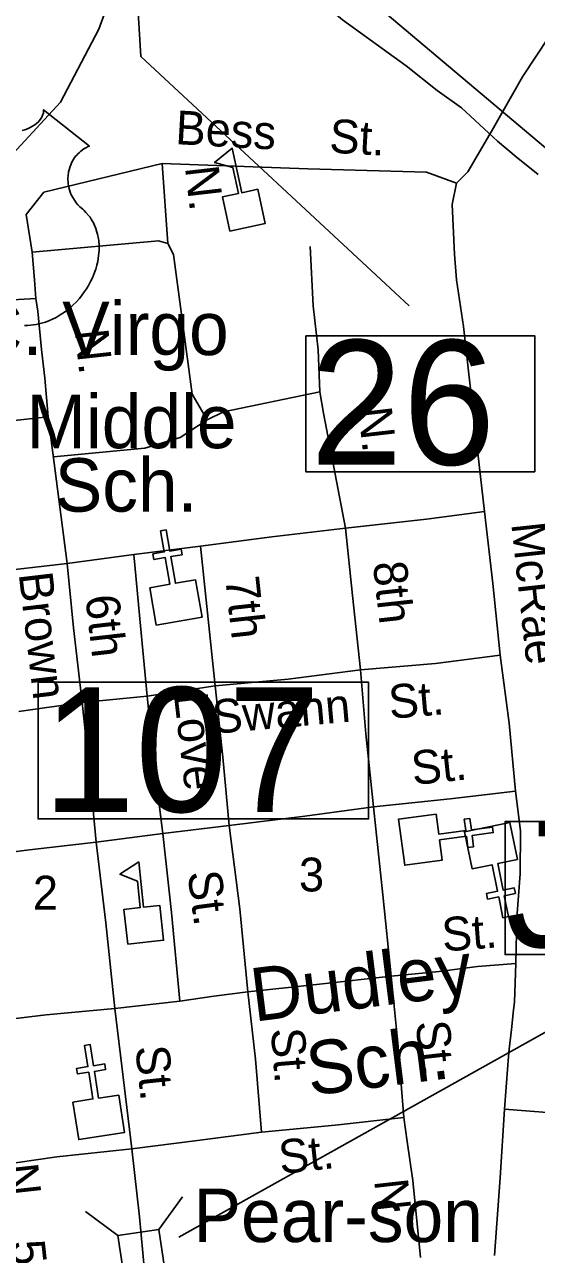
# Model space of a CAD drawing. Extents: x 2290055 to 2389491, y 66597 to 237875.
# Drawn here: x 2319151 to 2320590, y 181498 to 184954 of the extents above; entities that cross this region are included whole.
import ezdxf

# ---------------------------------------------------------------- set-up
doc = ezdxf.new("R2010")
doc.units = 0
for name, color, linetype in [('Exist Cultural Church CELL', 7, 'Continuous'), ('Exist Cultural Educational Facility High CELL', 7, 'Continuous'), ('Exist Cultural Educational Facility High Label', 7, 'Continuous'), ('Exist Cultural Educational Facility Middle CELL', 7, 'Continuous'), ('Exist Cultural Educational Facility Middle Label', 7, 'Continuous'), ('Exist Railroad Mainline', 7, 'Continuous'), ('Exist Road Non-System Structure Non-Sys Other CELL', 7, 'Continuous'), ('Exist Road Non-System Structure Non-Sys Other Number Label', 7, 'Continuous'), ('Exist Road Non-System Type 51', 7, 'Continuous'), ('Exist Road Non-System Type 51 Label', 7, 'Continuous'), ('Exist Road Primary US Shield CELL', 7, 'Continuous'), ('Exist Road Primary US Structure Cantilever Sign Number Label', 7, 'Continuous'), ('Exist Road Primary US Structure Standard Bridge Number Label', 7, 'Continuous')]:
    doc.layers.add(name, color=color, linetype=linetype)

msp = doc.modelspace()

# ---------------------------------------------------------------- linework, layer by layer
at = {"layer": 'Exist Cultural Church CELL'}
for points in [[(2319502.8, 183371.6), (2319558.9, 183381.3), (2319546, 183456.4), (2319514.4, 183450.9), (2319511.7, 183466.7), (2319543.3, 183472.1), (2319533.1, 183531.4), (2319548.9, 183534.1), (2319559, 183474.8), (2319590.6, 183480.2), (2319593.3, 183464.5), (2319561.8, 183459.1), (2319574.7, 183384), (2319631.5, 183393.7), (2319649.5, 183288.8), (2319520.8, 183266.6)], [(2320307.9, 182735.2), (2320315.5, 182678.8), (2320391, 182688.9), (2320386.7, 182720.6), (2320402.6, 182722.7), (2320406.8, 182691), (2320466.4, 182698.9), (2320468.5, 182683.1), (2320408.9, 182675.1), (2320413.1, 182643.4), (2320397.3, 182641.3), (2320393.1, 182673), (2320317.6, 182662.9), (2320325.1, 182605.8), (2320219.6, 182591.7), (2320202.3, 182721.1)], [(2320536.7, 182607.7), (2320481, 182596.2), (2320496.2, 182521.6), (2320527.6, 182528), (2320530.8, 182512.4), (2320499.4, 182506), (2320511.5, 182447), (2320495.8, 182443.8), (2320483.7, 182502.7), (2320452.4, 182496.3), (2320449.2, 182512), (2320480.5, 182518.4), (2320465.3, 182593), (2320408.8, 182581.6), (2320387.5, 182685.9), (2320515.4, 182712)], [(2319286.5, 181925.6), (2319342.7, 181934.5), (2319331.1, 182009.7), (2319299.4, 182004.8), (2319297, 182020.6), (2319328.6, 182025.5), (2319319.4, 182084.9), (2319335.2, 182087.4), (2319344.5, 182027.9), (2319376.1, 182032.9), (2319378.5, 182017.1), (2319346.9, 182012.2), (2319358.6, 181936.9), (2319415.6, 181945.7), (2319431.9, 181840.5), (2319302.8, 181820.4)]]:
    msp.add_lwpolyline(points, close=True, dxfattribs=at)
at = {"layer": 'Exist Cultural Educational Facility High CELL'}
msp.add_lwpolyline([(2319440.5, 182370), (2319430.1, 182467.4), (2319475.9, 182472.3), (2319467.9, 182547), (2319418.5, 182566.1), (2319471.7, 182601.1), (2319485.4, 182473.3), (2319531.2, 182478.2), (2319541.6, 182380.9)], close=True, dxfattribs=at)
at = {"layer": 'Exist Cultural Educational Facility Middle CELL'}
msp.add_lwpolyline([(2319727.9, 184374.2), (2319707.1, 184469.9), (2319752.1, 184479.6), (2319736.1, 184553), (2319685, 184566.7), (2319734.1, 184607.3), (2319761.4, 184481.7), (2319806.4, 184491.5), (2319827.2, 184395.8)], close=True, dxfattribs=at)
at = {"layer": 'Exist Railroad Mainline'}
for points in [[(2317368.7, 183162.4), (2317386.6, 183219.3), (2317454.9, 183335.6), (2317526.4, 183452.7), (2317687.4, 183621.9), (2317937.9, 183810.5), (2318299, 184030.9), (2318725.1, 184281.4), (2318969.1, 184431), (2319128.4, 184603.4), (2319252, 184736.8), (2319359.4, 184941.7), (2319414.7, 185094.6), (2319460.2, 185262.1), (2319475, 185682.8)], [(2320378.9, 184720.5), (2320310.7, 184769.6), (2320223.7, 184838.4), (2320044.1, 184968.1), (2319971.3, 185029.2), (2319914.8, 185076.4), (2319862.2, 185121.7), (2319815.5, 185167.1), (2319740.5, 185248.2)], [(2320594.4, 184533), (2320533, 184582.4), (2320480.6, 184626.5), (2320468.4, 184637.6), (2320378.9, 184720.5)]]:
    msp.add_lwpolyline(points, dxfattribs=at)
at = {"layer": 'Exist Road Non-System Structure Non-Sys Other CELL'}
for p, q in [((2319594.9, 181659.1), (2319527.7, 181568)), ((2319322.1, 181618), (2319413.2, 181550.8))]:
    msp.add_line(p, q, dxfattribs=at)
msp.add_lwpolyline([(2319527.7, 181568), (2319564.6, 181322.9), (2319450.1, 181305.7), (2319413.2, 181550.8)], close=True, dxfattribs=at)
at = {"layer": 'Exist Road Non-System Structure Non-Sys Other Number Label'}
msp.add_line((2319584.7, 181545.8), (2320938.2, 182302.9), dxfattribs=at)
msp.add_lwpolyline([(2321424.9, 182714.1), (2320501.6, 182714.1), (2320501.6, 182340.3), (2321424.9, 182340.3)], close=True, dxfattribs=at)
at = {"layer": 'Exist Road Non-System Type 51'}
for p, q in [((2319182.6, 184184.8), (2319178.8, 184237)), ((2319270.7, 183439.9), (2319217.4, 183851.6)), ((2320053.2, 183538.8), (2319846, 183514.6)), ((2319644.9, 183488.5), (2319457.8, 183465.4)), ((2319846, 183514.6), (2319644.9, 183488.5)), ((2319457.8, 183465.4), (2319270.7, 183439.9)), ((2320094.9, 183140.4), (2319892.1, 183114.3)), ((2319892.1, 183114.3), (2319686.7, 183096)), ((2319686.7, 183096), (2319495.6, 183066.5)), ((2319495.6, 183066.5), (2319312.5, 183049.4)), ((2319726.2, 182703.5), (2319539.1, 182680.3)), ((2319539.1, 182680.3), (2319352, 182656.8)), ((2319587.6, 182209.9), (2319404.3, 182188.6)), ((2320519.3, 182129.4), (2320525.5, 182184.9)), ((2320509.6, 182029.5), (2320510.6, 182042.5)), ((2320499.8, 181906.1), (2320509.6, 182029.5)), ((2320216.9, 181882.7), (2320221.7, 181848.7)), ((2320221.7, 181848.7), (2320226.4, 181815.3))]:
    msp.add_line(p, q, dxfattribs=at)
for points in [[(2320365.3, 184508.7), (2320396.7, 184540.5), (2320465.8, 184657.4), (2320550.4, 184807.6), (2320624.2, 184918.5), (2320669.5, 184987.6), (2320695.7, 185031.8), (2320710, 185078.3)], [(2319172, 184315), (2319154.7, 184420.6), (2319205.2, 184483.1), (2319537.9, 184563.7)], [(2319537.9, 184563.7), (2319947, 184548.8), (2320280.8, 184539.9), (2320365.3, 184508.7)], [(2319553.8, 184338.8), (2319537.9, 184563.7)], [(2320443.5, 183586.1), (2320406.5, 183913.8), (2320385.1, 184105.4), (2320364.8, 184237), (2320359.6, 184309), (2320352.6, 184448.7), (2320365.3, 184508.7)], [(2319664.2, 183843.6), (2319622.3, 183916), (2319569, 184308.3), (2319553.8, 184338.8), (2319527.2, 184346.4), (2319172, 184315)], [(2319980.4, 183922.3), (2319976.3, 184040.3), (2319962, 184164), (2319953.5, 184330.4)], [(2319178.8, 184237), (2319172, 184315)], [(2319182.6, 184184.8), (2319084.6, 184179.1), (2318946.8, 184162.6), (2318817, 184152.3), (2318711.2, 184136.5), (2318647.3, 184133.3), (2318597.6, 184120.6), (2318559.9, 184095.9), (2318498.4, 184062.8), (2318461, 184038.1), (2318381.3, 183989.4)], [(2319217.4, 183851.6), (2319207.5, 183961), (2319198.1, 184040.9), (2319188.3, 184148.7), (2319182.6, 184184.8)], [(2319980.4, 183922.3), (2319709.9, 183866.4), (2319664.2, 183843.6), (2319588.1, 183794.1), (2319489.1, 183763.6), (2319232, 183739.5)], [(2320053.2, 183538.8), (2319991.3, 183862.5), (2319980.4, 183922.3)], [(2319217.4, 183851.6), (2319121.6, 183841.4), (2318985.8, 183831), (2318865.9, 183817.1), (2318762.1, 183805.1), (2318642.3, 183799.2), (2318582.4, 183790), (2318492.5, 183782.6), (2318409.4, 183771.5)], [(2320443.5, 183586.1), (2320280.3, 183563.9), (2320053.2, 183538.8)], [(2320487.4, 183181.9), (2320467.6, 183383.3), (2320443.5, 183586.1)], [(2320053.2, 183538.8), (2320072.8, 183349.6), (2320094.9, 183140.4)], [(2319686.7, 183096), (2319664.5, 183301.3), (2319644.9, 183488.5)], [(2319457.8, 183465.4), (2319475.1, 183283.9), (2319495.6, 183066.5)], [(2319270.7, 183439.9), (2319083, 183418.5)], [(2319312.5, 183049.4), (2319288.1, 183258.5), (2319270.7, 183439.9)], [(2320487.4, 183181.9), (2320306.5, 183158.6), (2320094.9, 183140.4)], [(2320530.7, 182799.6), (2320513, 182990.9), (2320487.4, 183181.9)], [(2320094.9, 183140.4), (2320110.2, 182960.9), (2320132.1, 182755.6)], [(2319726.2, 182703.5), (2319708.5, 182895.1), (2319686.7, 183096)], [(2319312.5, 183049.4), (2319134.7, 183023.5)], [(2319352, 182656.8), (2319334.3, 182846.1), (2319312.5, 183049.4)], [(2319495.6, 183066.5), (2319515.4, 182873.3), (2319539.1, 182680.3)], [(2320530.7, 182799.6), (2320347.5, 182778.3), (2320132.1, 182755.6)], [(2320531.9, 182315.3), (2320534.7, 182443.4), (2320543.9, 182567.8), (2320545, 182688), (2320530.7, 182799.6)], [(2320132.1, 182755.6), (2319939.1, 182729.9), (2319726.2, 182703.5)], [(2320132.1, 182755.6), (2320158, 182508.5), (2320181.1, 182279.4)], [(2319778.5, 182235.6), (2319755.5, 182468.6), (2319726.2, 182703.5)], [(2319352, 182656.8), (2319164.8, 182635.3), (2318957.7, 182609)], [(2319404.3, 182188.6), (2319379, 182429.8), (2319352, 182656.8)], [(2319539.1, 182680.3), (2319563.9, 182459.1), (2319587.6, 182209.9)], [(2320531.9, 182315.3), (2320424.2, 182307.1), (2320316.5, 182293), (2320181.1, 182279.4)], [(2320525.5, 182184.9), (2320527.9, 182207.1), (2320531.9, 182315.3)], [(2320181.1, 182279.4), (2319979.8, 182257.6), (2319778.5, 182235.6)], [(2320181.1, 182279.4), (2320200.4, 182092.1), (2320216.9, 181882.7)], [(2319778.5, 182235.6), (2319683.2, 182223.9), (2319587.6, 182209.9)], [(2319816.5, 181840.9), (2319800.2, 182046.4), (2319778.5, 182235.6)], [(2319404.3, 182188.6), (2319211, 182171.1), (2319007.9, 182147)], [(2319452.1, 181794.3), (2319428, 181995.6), (2319404.3, 182188.6)], [(2320510.6, 182042.5), (2320513.2, 182074.6), (2320519.3, 182129.4)], [(2320472.1, 181494.7), (2320487.4, 181713.3), (2320499.8, 181906.1)], [(2320893.2, 181875.4), (2320704.6, 181890.2), (2320499.8, 181906.1)], [(2320216.9, 181882.7), (2320023.8, 181861), (2319816.5, 181840.9)], [(2319816.5, 181840.9), (2319637.2, 181817.8), (2319452.1, 181794.3)], [(2319452.1, 181794.3), (2319240.9, 181772.2), (2319072.3, 181747.6)], [(2319452.1, 181794.3), (2319473.8, 181603.2), (2319487.4, 181451.7)], [(2320226.4, 181815.3), (2320241.9, 181705.8), (2320264.3, 181488.5)]]:
    msp.add_lwpolyline(points, dxfattribs=at)
at = {"layer": 'Exist Road Primary US Shield CELL'}
msp.add_lwpolyline([(2319143.9, 184657.1), (2319151.6, 184659.1), (2319158.6, 184661.6), (2319164.8, 184664.3), (2319172.7, 184668.5), (2319179.2, 184672.5), (2319183.9, 184676.3), (2319189.5, 184681.5), (2319194.8, 184687.6), (2319198, 184692.1), (2319200.2, 184696.7), (2319202.2, 184701.6), (2319203.5, 184706.8), (2319204.1, 184711.3), (2319204.2, 184715.1), (2319332.8, 184612.6), (2319329.8, 184611.5), (2319322.8, 184608.1), (2319317.2, 184604.8), (2319308.4, 184598.6), (2319304.6, 184595.2), (2319300.8, 184591.6), (2319297.3, 184587.8), (2319294.2, 184584.2), (2319290.5, 184579), (2319287.2, 184573.9), (2319283.9, 184568.2), (2319281.5, 184563.2), (2319277.6, 184552.9), (2319275.7, 184546.4), (2319274.4, 184540.8), (2319272.9, 184529.3), (2319272.5, 184523.9), (2319272.5, 184518.5), (2319272.8, 184512.8), (2319273.4, 184507.3), (2319274.4, 184501.6), (2319275.3, 184496.6), (2319276.9, 184490.4), (2319279.1, 184483.3), (2319282, 184476.4), (2319287.8, 184465.2), (2319295.4, 184453.8), (2319300.8, 184447.4), (2319306.1, 184442), (2319314, 184435.3), (2319318.3, 184431.5), (2319323.3, 184426.5), (2319331.3, 184417.2), (2319334.6, 184412.8), (2319337.9, 184407.8), (2319340.9, 184402.8), (2319344, 184397.3), (2319346.4, 184392.5), (2319350.9, 184381.5), (2319354.2, 184370.8), (2319355.7, 184365.1), (2319358.1, 184352.5), (2319359, 184346.3), (2319360, 184334), (2319360.1, 184319.1), (2319358.9, 184305), (2319356.3, 184288.5), (2319354.1, 184278.6), (2319350.7, 184267.1), (2319347.4, 184257.2), (2319341.5, 184242.5), (2319336.3, 184231.9), (2319329.6, 184219.4), (2319324.9, 184211.9), (2319319.5, 184203.8), (2319312.8, 184194.6), (2319304.9, 184184.7), (2319295.4, 184174.3), (2319287.7, 184166.6), (2319277.7, 184157.6), (2319271.6, 184152.6), (2319263, 184146.1), (2319251.1, 184138.2), (2319239.4, 184131.4), (2319229.5, 184126.3), (2319220.7, 184122.5), (2319209.3, 184118.2), (2319190.3, 184112.9), (2319183.4, 184111.5), (2319175.2, 184110.3), (2319167.5, 184109.5), (2319160.1, 184109.1), (2319150, 184109.1)], dxfattribs=at)
at = {"layer": 'Exist Road Primary US Structure Cantilever Sign Number Label'}
msp.add_line((2319734.2, 185350.9), (2321369, 183972.8), dxfattribs=at)
at = {"layer": 'Exist Road Primary US Structure Standard Bridge Number Label'}
msp.add_lwpolyline([(2319437, 185533.3), (2319477.5, 184864.5), (2320232, 184163.7)], dxfattribs=at)
for points in [[(2319941, 184079.9), (2320585.1, 184079.9), (2320585.1, 183697.6), (2319941, 183697.6)], [(2319188.7, 183106), (2320117.7, 183106), (2320117.7, 182721.9), (2319188.7, 182721.9)]]:
    msp.add_lwpolyline(points, close=True, dxfattribs=at)

# ---------------------------------------------------------------- texts
at = {"layer": 'Exist Cultural Educational Facility High Label'}
for s, rotation, p in [('Dudley', 7.1319, (2319796.2, 182151.6)), (' Sch.', 7.1316, (2319897.5, 181936.6))]:
    msp.add_text(s, height=150, rotation=rotation, dxfattribs=at).set_placement(p)
msp.add_text('Pear-son', height=150, dxfattribs=at).set_placement((2319625.4, 181532.4))
at = {"layer": 'Exist Cultural Educational Facility Middle Label'}
for s, p in [('D.C. Virgo', (2318799.5, 184025.5)), ('Middle', (2319156, 183763.8)), ('Sch.', (2319235.3, 183585.5))]:
    msp.add_text(s, height=150, dxfattribs=at).set_placement(p)
at = {"layer": 'Exist Road Non-System Structure Non-Sys Other Number Label'}
msp.add_text('J33', height=350, dxfattribs=at).set_placement((2320502.2, 182361.9))
at = {"layer": 'Exist Road Non-System Type 51 Label'}
for s, rotation, p in [('Bess', 356.8438, (2319573.3, 184618.5)), ('St.', 356.8438, (2320006, 184594.7)), ('N.', 276.5691, (2319601.5, 184553.3)), ('N.', 276.2475, (2319291.3, 184094.2)), ('N.', 276.5993, (2320087.9, 183875)), ('McRae', 276.2145, (2320518.9, 183551.5)), ('8th', 276.2812, (2320129.8, 183441.6)), ('Brown', 276.7158, (2319133.9, 183411)), ('7th', 276.1866, (2319714.7, 183399.3)), ('6th', 276.488, (2319321.2, 183347.3)), ('Love', 276.6338, (2319570.3, 183071.3)), ('St.', 4.9224, (2320178.2, 183002.9)), ('Swann', 5.0938, (2319682.9, 182960.8)), ('St.', 6.0001, (2320243.3, 182816.8)), ('St.', 277.5465, (2319608.4, 182571.1)), ('St.', 4.3572, (2320327.3, 182349)), ('St.', 276.611, (2320249.6, 182150.3)), ('St.', 274.5477, (2319842.8, 182131.3)), ('St.', 276.0438, (2319461.6, 182080.8)), ('St.', 6.429, (2319870.5, 181723.3)), ('N.', 276.3606, (2319093.5, 181748.8)), ('N.', 276.4193, (2320133.4, 181705.5)), ('5th', 276.2695, (2319112, 181533.5))]:
    msp.add_text(s, height=95, rotation=rotation, dxfattribs=at).set_placement(p)
for s, p in [('3', (2319922.2, 182517.9)), ('2', (2319174, 182467.1))]:
    msp.add_text(s, height=95, dxfattribs=at).set_placement(p)
at = {"layer": 'Exist Road Primary US Structure Standard Bridge Number Label'}
for s, p in [('26', (2319953.6, 183717.4)), ('107', (2319201.3, 182741.6))]:
    msp.add_text(s, height=350, dxfattribs=at).set_placement(p)

doc.saveas('drawing.dxf')
